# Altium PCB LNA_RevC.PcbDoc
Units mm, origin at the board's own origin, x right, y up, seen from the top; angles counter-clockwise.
Board outline 54 x 28 mm, 2 copper layers (Top Layer, Bottom Layer); 48 components, 25 nets, 118 pads, 134 vias.
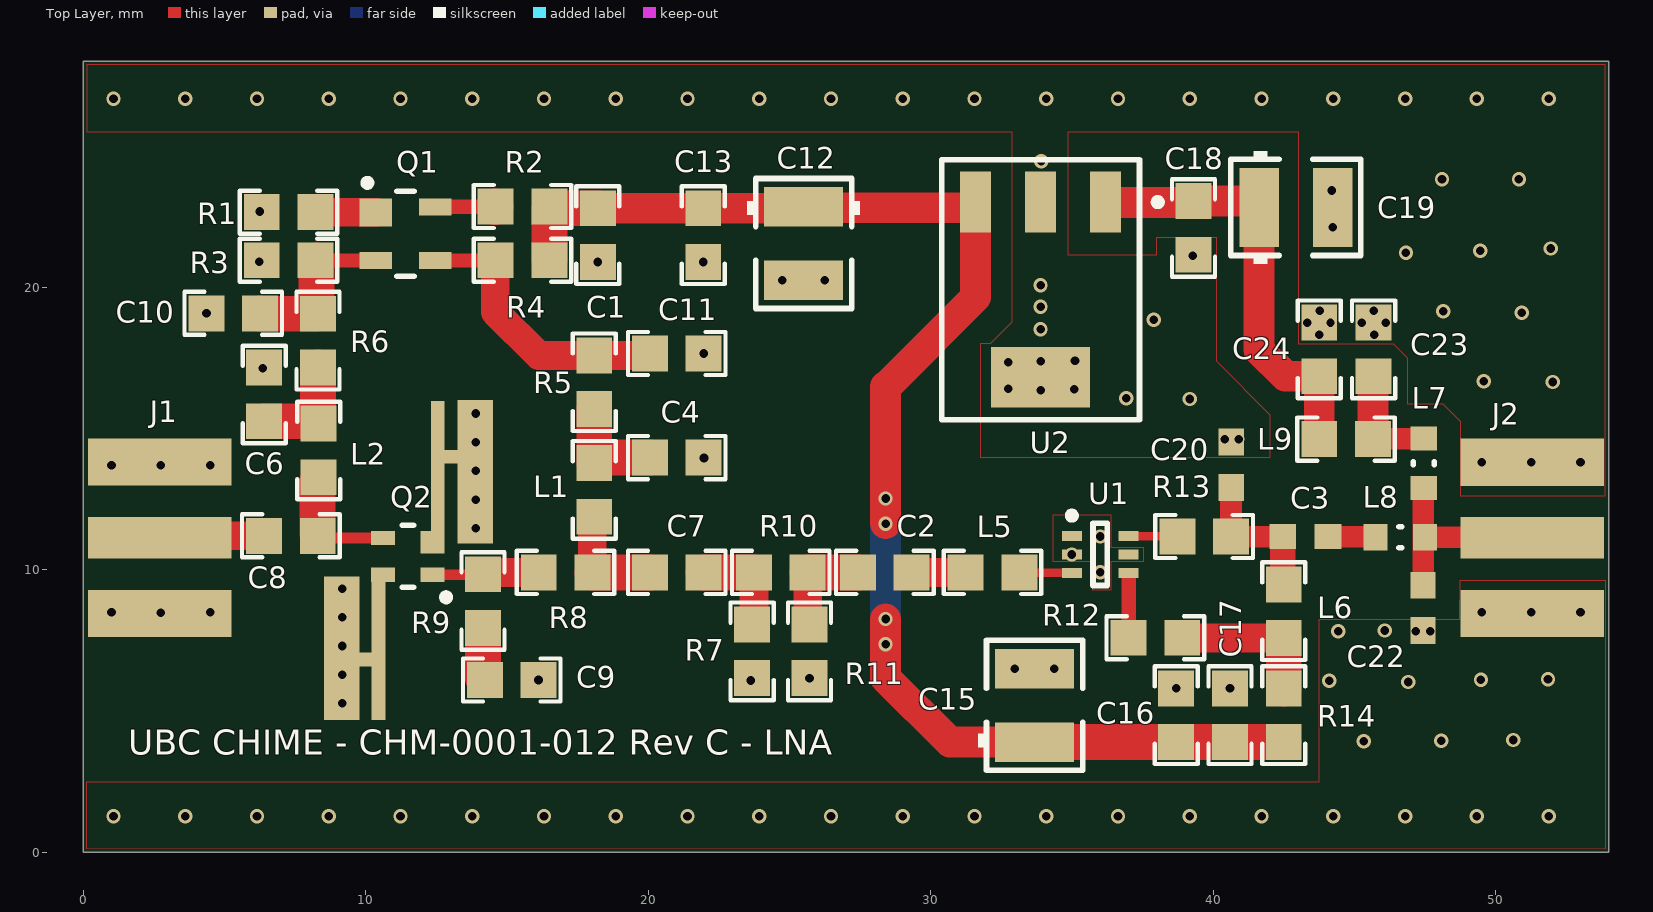
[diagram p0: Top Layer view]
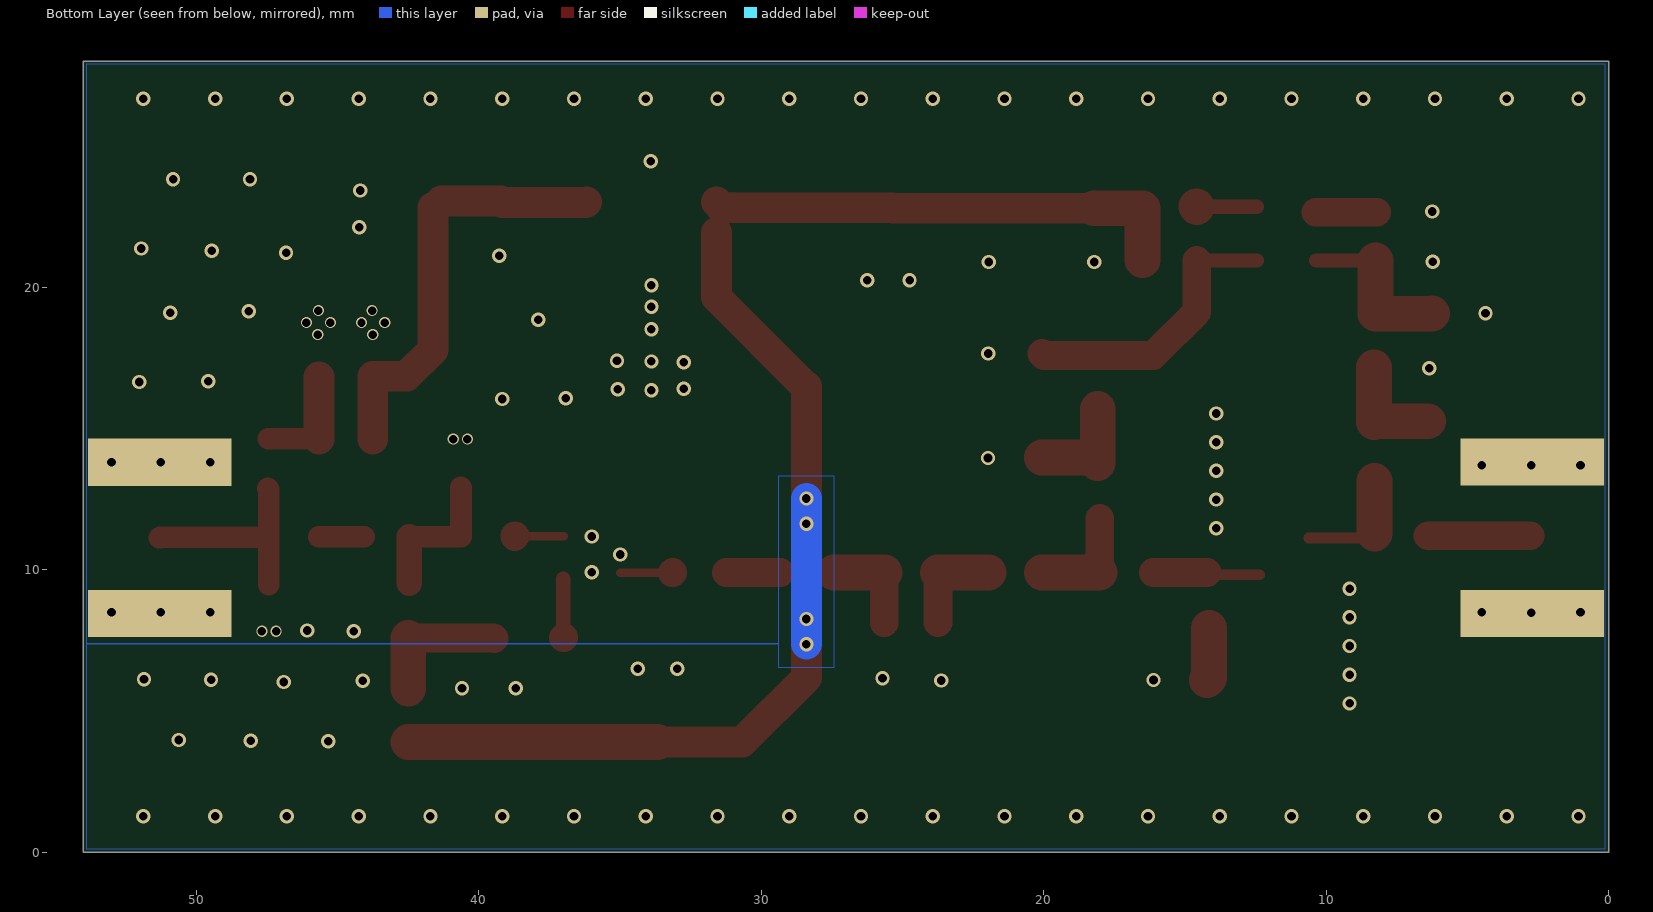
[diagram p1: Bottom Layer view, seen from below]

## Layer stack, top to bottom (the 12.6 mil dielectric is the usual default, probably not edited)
Top Solder: solder mask 0.0102, Solder Resist, Dk 3.5
Top Layer: signal copper 0.0356
Dielectric1: dielectric 0.32, FR-4, Dk 4.8
Bottom Layer: signal copper 0.0356
Bottom Solder: solder mask 0.0102, Solder Resist, Dk 3.5

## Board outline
0,0 0,28 54,28 54,0

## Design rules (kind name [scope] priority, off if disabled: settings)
AssemblyTestPointUsage [All] p0: scope1count=1 scope1_0_kind=Board scope1_0_value=Board scope2count=1 scope2_0_kind=Board scope2_0_value=Board commentlength=0
AssemblyTestpoint [All] p0: scope1count=1 scope1_0_kind=Board scope1_0_value=Board scope2count=1 scope2_0_kind=Board scope2_0_value=Board commentlength=0
Clearance [All] p0: scope1count=1 scope1_0_kind=Board scope1_0_value=Board scope2count=1 scope2_0_kind=Board scope2_0_value=Board commentlength=0 gap=0.1
Clearance Clearance_1 [All] p0: scope1count=1 scope1_0_kind=Board scope1_0_value=Board scope2count=1 scope2_0_kind=Board scope2_0_value=Board commentlength=0 gap=0.1
Clearance [All] p1: gap=0.1
Clearance Clearance_1 [All] p2: gap=0.1
ComponentClearance [All] p0: scope1count=1 scope1_0_kind=Board scope1_0_value=Board scope2count=1 scope2_0_kind=Board scope2_0_value=Board commentlength=0 gap=0 collisioncheckmode=3
ComponentClearance [All] p1: gap=0 collisioncheckmode=3 verticalgap=0 showdistances=FALSE
DiffPairsRouting [All] p0: scope1count=1 scope1_0_kind=Board scope1_0_value=Board scope2count=1 scope2_0_kind=Board scope2_0_value=Board commentlength=0
FabricationTestPointUsage [All] p0: scope1count=1 scope1_0_kind=Board scope1_0_value=Board scope2count=1 scope2_0_kind=Board scope2_0_value=Board commentlength=0 valid=0 allowmultiple=FALSE
FabricationTestpoint [All] p0: scope1count=1 scope1_0_kind=Board scope1_0_value=Board scope2count=1 scope2_0_kind=Board scope2_0_value=Board commentlength=0 side=3 testpointundercomponent=TRUE minsize=1.016 maxsize=2.54 preferedsize=1.524 minholesize=0 maxholesize=1.016 preferedholesize=0.813 testpointgrid=0.025
FanoutControl Fanout_BGA [All] p0 off: scope1count=1 scope1_0_kind=Board scope1_0_value=Board scope2count=1 scope2_0_kind=Board scope2_0_value=Board commentlength=69 // Protel DXP Scope 1 Expression Was: IsBGA   Fanout_BGA (Default Rule)
FanoutControl Fanout_LCC [All] p0 off: scope1count=1 scope1_0_kind=Board scope1_0_value=Board scope2count=1 scope2_0_kind=Board scope2_0_value=Board commentlength=69 // Protel DXP Scope 1 Expression Was: IsLCC   Fanout_LCC (Default Rule)
FanoutControl Fanout_SOIC [All] p0 off: scope1count=1 scope1_0_kind=Board scope1_0_value=Board scope2count=1 scope2_0_kind=Board scope2_0_value=Board commentlength=71 // Protel DXP Scope 1 Expression Was: IsSOIC   Fanout_SOIC (Default Rule)
FanoutControl Fanout_Small [All] p0 off: scope1count=1 scope1_0_kind=Board scope1_0_value=Board scope2count=1 scope2_0_kind=Board scope2_0_value=Board commentlength=84 // Protel DXP Scope 1 Expression Was: (CompPinCount < 5)   Fanout_Small (Default Rule)
FanoutControl Fanout_Default [All] p0: scope1count=1 scope1_0_kind=Board scope1_0_value=Board scope2count=1 scope2_0_kind=Board scope2_0_value=Board commentlength=30 // Fanout_Default (Default Rule)
Height [All] p0: scope1count=1 scope1_0_kind=Board scope1_0_value=Board scope2count=1 scope2_0_kind=Board scope2_0_value=Board commentlength=0
HoleSize [All] p0: scope1count=1 scope1_0_kind=Board scope1_0_value=Board scope2count=1 scope2_0_kind=Board scope2_0_value=Board commentlength=0 absolutevalues=TRUE maxlimit=5.54 minlimit=0.025 maxpercent=80.000 minpercent=20.000
HoleSize [All] p1: absolutevalues=TRUE maxlimit=5.54 minlimit=0.025 maxpercent=80.000 minpercent=20.000
HoleToHoleClearance [All] p0: scope1count=1 scope1_0_kind=Board scope1_0_value=Board scope2count=1 scope2_0_kind=Board scope2_0_value=Board commentlength=0
HoleToHoleClearance [All] p1: gap=0.1 allowstackedmicrovias=TRUE
LayerPairs [All] p0: scope1count=1 scope1_0_kind=Board scope1_0_value=Board scope2count=1 scope2_0_kind=Board scope2_0_value=Board commentlength=0 enforce=TRUE
MinimumSolderMaskSliver [All] p0: scope1count=1 scope1_0_kind=Board scope1_0_value=Board scope2count=1 scope2_0_kind=Board scope2_0_value=Board commentlength=0
MinimumSolderMaskSliver [All] p1: minsoldermaskwidth=0.01
NetAntennae [All] p0: scope1count=1 scope1_0_kind=Board scope1_0_value=Board scope2count=1 scope2_0_kind=Board scope2_0_value=Board commentlength=0
PasteMaskExpansion [All] p0: scope1count=1 scope1_0_kind=Board scope1_0_value=Board scope2count=1 scope2_0_kind=Board scope2_0_value=Board commentlength=0 expansion=0
PlaneClearance [All] p0: scope1count=1 scope1_0_kind=Board scope1_0_value=Board scope2count=1 scope2_0_kind=Board scope2_0_value=Board commentlength=0 clearance=0.2
PlaneClearance [All] p1: clearance=0.2
PlaneConnect [All] p0: scope1count=1 scope1_0_kind=Board scope1_0_value=Board scope2count=1 scope2_0_kind=Board scope2_0_value=Board commentlength=0 planeconnectstyle=Direct reliefexpansion=0.508 reliefentries=4 reliefconductorwidth=0.254 reliefairgap=0.254
PlaneConnect [All] p1: planeconnectstyle=Direct reliefexpansion=0.508 reliefentries=4 reliefconductorwidth=0.254 reliefairgap=0.254
PolygonConnect [All] p0: scope1count=1 scope1_0_kind=Board scope1_0_value=Board scope2count=1 scope2_0_kind=Board scope2_0_value=Board commentlength=0 connectstyle=Direct reliefconductorwidth=0.254 reliefentries=4 polygonreliefangle="90 Angle"
PolygonConnect [All] p1: connectstyle=Direct reliefconductorwidth=0.254 reliefentries=4 polygonreliefangle="90 Angle" airgapwidth=0.254
RoutingCorners [All] p0: scope1count=1 scope1_0_kind=Board scope1_0_value=Board scope2count=1 scope2_0_kind=Board scope2_0_value=Board commentlength=0 cornerstyle=45-Degree minsetback=2.54 maxsetback=2.54
RoutingLayers [All] p0: scope1count=1 scope1_0_kind=Board scope1_0_value=Board scope2count=1 scope2_0_kind=Board scope2_0_value=Board commentlength=0 top layer=Automatic bottom layer=Automatic
RoutingPriority [All] p0: scope1count=1 scope1_0_kind=Board scope1_0_value=Board scope2count=1 scope2_0_kind=Board scope2_0_value=Board commentlength=0
RoutingTopology [All] p0: scope1count=1 scope1_0_kind=Board scope1_0_value=Board scope2count=1 scope2_0_kind=Board scope2_0_value=Board commentlength=0 topology=Shortest
RoutingVias [All] p0: scope1count=1 scope1_0_kind=Board scope1_0_value=Board scope2count=1 scope2_0_kind=Board scope2_0_value=Board commentlength=0 holewidth=0.711 width=1.27 viastyle="Through Hole" minholewidth=0.711 minwidth=0.27 maxholewidth=0.711 maxwidth=5.27
RoutingVias [All] p1: holewidth=0.711 width=1.27 viastyle="Through Hole" minholewidth=0.711 minwidth=0.27 maxholewidth=0.711 maxwidth=5.27
ShortCircuit [All] p0: scope1count=1 scope1_0_kind=Board scope1_0_value=Board scope2count=1 scope2_0_kind=Board scope2_0_value=Board commentlength=0 allowed=FALSE
SilkToBoardRegionClearance [All] p0: scope1count=1 scope1_0_kind=Board scope1_0_value=Board scope2count=1 scope2_0_kind=Board scope2_0_value=Board commentlength=0
SilkToSilkClearance [All] p0: scope1count=1 scope1_0_kind=Board scope1_0_value=Board scope2count=1 scope2_0_kind=Board scope2_0_value=Board commentlength=0
SilkToSilkClearance [All] p1: silktosilkclearance=0
SilkToSolderMaskClearance SilkscreenOverComponentPads [All] p0 off: scope1count=1 scope1_0_kind=Board scope1_0_value=Board scope2count=1 scope2_0_kind=Board scope2_0_value=Board commentlength=44 // Protel DXP Scope 1 Expression Was: IsPad
SilkToSolderMaskClearance SilkscreenOverComponentPads [IsPad] p1: minsilkscreentomaskgap=0.01 clearancetoexposedcopper=TRUE
SolderMaskExpansion [All] p0: scope1count=1 scope1_0_kind=Board scope1_0_value=Board scope2count=1 scope2_0_kind=Board scope2_0_value=Board commentlength=0 expansion=0.05
SolderMaskExpansion [All] p1: expansion=0.05
UnRoutedNet [All] p0: scope1count=1 scope1_0_kind=Board scope1_0_value=Board scope2count=1 scope2_0_kind=Board scope2_0_value=Board commentlength=0
UnpouredPolygon [All] p0: scope1count=1 scope1_0_kind=Board scope1_0_value=Board scope2count=1 scope2_0_kind=Board scope2_0_value=Board commentlength=0
Width [All] p0: scope1count=1 scope1_0_kind=Board scope1_0_value=Board scope2count=1 scope2_0_kind=Board scope2_0_value=Board commentlength=0 maxlimit=25 minlimit=0.1 preferedwidth=0.254
Width [All] p1: maxlimit=25 minlimit=0.1 preferedwidth=0.254
22 further rules are at their usual default settings.

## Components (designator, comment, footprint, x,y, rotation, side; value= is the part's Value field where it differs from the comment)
C1 "C0805_1n" "0805 LRC" 18.215,21.844 r90 top
C2 "C0805_100p" "0805 LRC" 28.375,9.906 r0 top
C3 "C0603_2p7" C1608-0603 43.259,11.176 r180 top
C4 "C0805_15p" "0805 LRC" 21.009,13.97 r0 top
C6 "C0805_22p" "0805 LRC" 6.404,16.205 r270 top
C7 "C0805_1n" "0805 LRC" 21.009,9.906 r180 top
C8 "C0805_220p" "0805 LRC" 7.35,11.2 r0 top
C9 "C0805_2p2" "0805 LRC" 15.167,6.096 r180 top
C10 "C0805_1n" "0805 LRC" 5.312,19.075 r0 top
C11 "C0805_1n" "0805 LRC" 21.009,17.653 r180 top
C12 "Comment" CC3528 25.5,21.55 r270 top
C13 "C0805_u1" "0805 LRC" 21.949,21.844 r90 top
C15 "Comment" CC3528 33.675,5.2 r90 top
C16 "C0805_1n" "0805 LRC" 38.687,4.851 r90 top
C17 "C0805_u1" "0805 LRC" 40.592,4.851 r270 top
C18 "C0805_u1" "0805 LRC" 39.3,22.1 r90 top
C19 "Comment" CC3528 42.925,22.825 r0 top
C20 "C0603_3p9" C1608-0603 40.643,13.716 r270 top
C22 "C0603_2p7" C1608-0603 47.425,8.65 r90 top
C23 "C0805_1n" "0805 LRC" 45.675,17.8 r270 top
C24 "C0805_1n" "0805 LRC" 43.75,17.8 r270 top
J1 "SMA-Edgemount" SMA_EDGEMOUNT#1 2.859,11.128 r0 top
J2 "SMA-Edgemount" SMA_EDGEMOUNT#2 50.956,11.128 r0 top
L1 "Ind0805_22nH" "0805 LRC" 18.088,12.827 r90 top
L2 "Ind0805_82nH" "0805 LRC" 8.334,14.224 r90 top
L5 "Ind0805_6n8H" "0805 LRC" 32.185,9.906 r0 top
L6 "Ind0805_47nH" "0805 LRC" 42.497,8.534 r270 top
L7 "Ind0603_15nH" R0603 47.45,13.767 r90 top
L8 "Ind0603_15nH" R0603 46.625,11.15 r0 top
L9 "Ind0805_100nH" "0805 LRC" 44.7,14.625 r0 top
Q1 "BCV62" SOT143B_N 11.408,21.895 r0 top
Q2 "ATF-54143" SOT130P210X100-4AL 11.492,10.475 r180 top
R1 "R0805_3k32" "0805 LRC" 7.268,22.657 r0 top
R2 "R0805_511R" "0805 LRC" 15.548,22.86 r0 top
R3 "R0805_562R" "0805 LRC" 7.268,20.955 r0 top
R4 "R0805_10R" "0805 LRC" 15.548,20.955 r0 top
R5 "R0805_15R" "0805 LRC" 18.088,16.637 r90 top
R6 "R0805_100R" "0805 LRC" 8.309,18.11 r90 top
R7 "R0805" "0805 LRC" 23.676,7.112 r90 top
R8 "R0805_10R" "0805 LRC" 17.072,9.906 r0 top
R9 "R0805_12R7" "0805 LRC" 14.151,8.89 r90 top
R10 "R0805_0R" "0805 LRC" 24.692,9.906 r0 top
R11 "R0805" "0805 LRC" 25.708,7.112 r90 top
R12 "R0805_750R" "0805 LRC" 37.951,7.595 r0 top
R13 "R0805_0R" "0805 LRC" 39.678,11.176 r0 top
R14 "R0805_0R" "0805 LRC" 42.497,4.851 r270 top
U1 "MGA-62563" SOT-363/SC-70 35.995,10.541 r0 top
U2 "LT1129IST-5" SOT-223 33.887,19.914 r180 top

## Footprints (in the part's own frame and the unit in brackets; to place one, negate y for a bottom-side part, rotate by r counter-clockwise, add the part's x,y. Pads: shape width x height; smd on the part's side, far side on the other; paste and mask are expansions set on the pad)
"0805 LRC" [mm] "Generic 0805 reduced footprint"
  rect 1.27x1.27 smd: 1(-0.95,0) 2(0.95,0)
  silkscreen extent -1.73,-0.76 1.73,0.76
C1608-0603 [mm] "Chip Capacitor, 2-Leads, Body 1.60x0.80mm, IPC Medium Density"
  rect 0.95x0.9 smd: 1(-0.8,0) 2(0.8,0)
CC3528 [mm]
  rect 1.4x2.8 smd: 1(-1.3,0) 2(1.3,0)
  silkscreen extent -2.3,-2 2.3,2
R0603 [mm] "Chip Resistor, 2-Leads, Body 1.60x0.80mm, IPC Medium Density"
  rect 0.85x0.95 smd: 1(-0.875,0) 2(0.875,0)
  silkscreen extent -0.05,-0.38 0.05,0.38
SMA_EDGEMOUNT#1 [mm]
  rect 5.08x1.47 smd: 1(-0.159,0)
  rect 5.08x1.67 smd: 2(-0.159,-2.678) 2(-0.159,2.682)
  rect 5.08x1.67 smd far side: 2(-0.159,-2.678) 2(-0.159,2.682)
SMA_EDGEMOUNT#2 [mm]
  rect 5.08x1.47 smd: 1(0.344,0)
  rect 5.08x1.67 smd: 2(0.344,-2.681) 2(0.344,2.679)
  rect 5.08x1.67 smd far side: 2(0.344,-2.681) 2(0.344,2.679)
SOT130P210X100-4AL [mm] "SOT343, 4-Leads, Body 2x1.3 mm, Pitch 1.3mm, Lead Span 2.1mm, IPC High Density"
  rect 0.85x0.5 smd: 1(-0.875,0.65) 3(0.875,-0.65) 4(0.875,0.65)
  rect 0.85x0.8 smd: 2(-0.875,-0.5)
  silkscreen extent -1.48,-1.1 0.2,1.57
SOT143B_N [mm] "SOT143, 4-Leads, Body 2.9x1.3mm, Pitch 1.9mm, Lead Span 2.3mm, IPC Medium Density"
  rect 1.15x1 smd: 1(-1.05,0.75)
  rect 1.15x0.6 smd: 2(-1.05,-0.95) 3(1.05,-0.95) 4(1.05,0.95)
  silkscreen extent -1.47,-1.5 0.3,1.92
SOT-223 [mm]
  rect 1.1x2.15 smd: 1(-2.3,-3.1) 2(0,-3.1) 3(2.3,-3.1)
  rect 3.5x2.15 smd: 4(0,3.1)
  silkscreen extent -4.27,-4.6 3.5,4.6
SOT-363/SC-70 [mm] "SOT23, 6-Leads, Body 2.3x2.4mm (max), Pitch 0.65mm, IPC Medium Density"
  rect 0.7x0.35 smd: 1(-1,0.65) 2(-1,0) 3(-1,-0.65) 4(1,-0.65) 5(1,0) 6(1,0.65)
  silkscreen extent -1.12,-1.1 0.25,1.5

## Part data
C1 C7 C10 C11 C16 C23 C24: "1nF Ceramic NPO 0805 Capacitor"
C2: "100pF Ceramic NPO 0805 Capacitor"
C3 C22: "2.7pf  +- .1pf 50V NPO(COG)"
C4: "15pF Ceramic NPO 0805 Capacitor"
C6: "22pF Ceramic NPO 0805 Capacitor"
C8: library part C0805_100p, "220pF Ceramic NPO 0805 RF Capacitor"
C9: "2p2 Ceramic NPO 0805 Capacitor"
C12 C15 C19: library part "Cap Tant 10uF 25V B-Size Low ESR", "Cap Tant 10uF 25V Low ESR"
C13 C17 C18: "u1 Ceramic X7R 0805 Capacitor"
C20: "3.9pf  +-.1pf 0603 50V NPO"
J1 J2: library part "SMA LTI", "SMA long edge launch connectors female"
L1: "22nH 0805 Inductor"
L2: "82nH 0805 Inductor"
L5: "6n8H 0805 Inductor"
L6: "47nH 0805 Inductor"
L7 L8: "15nH 2% 0603"
L9: "100nH 0805 Inductor"
Q1: "PNP General-purpose Double Transistor"
Q2: "Avagotech GaAs FET enhancement pHEMT"
R1: "3k32 0805 0.1% 10ppm Resistor"
R2: "511R 0805 0.1% 10ppm Resistor"
R3: "562R 0805 0.1% 10ppm Resistor"
R4 R8: "10R 0805 0.1% 10ppm Resistor"
R5: "15R 0805 0.1% 10ppm Resistor"
R6: "100R 0805 0.1% 10ppm Resistor"
R7 R11: "??? 0805 1% Resistor"
R9: "12R7 0805 0.1% 10ppm Resistor"
R10 R13 R14: "0R 0805 1% Resistor"
R12: "750R 0805 0.1% 10ppm Resistor"
U1: "Low Noise RF Amplifier"
U2: "LDO +5V Regulator 700mA"

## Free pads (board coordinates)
  rect 1.27x5.08 smd: 0(9.15,7.225) 0(13.875,13.475)
  rect 1.016x0.483 smd: 2(9.925,6.825) 2(13.025,14)
  rect 0.483x5.334 smd: 2(10.45,7.35) 2(12.55,13.3)

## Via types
v1: diameter 0.508, hole 0.305, Top Layer to Bottom Layer, 109 vias
v2: diameter 0.508, hole 0.305, Top Layer to Bottom Layer, tented both sides, 13 vias
v3: diameter 0.4, hole 0.3, Top Layer to Bottom Layer, 12 vias

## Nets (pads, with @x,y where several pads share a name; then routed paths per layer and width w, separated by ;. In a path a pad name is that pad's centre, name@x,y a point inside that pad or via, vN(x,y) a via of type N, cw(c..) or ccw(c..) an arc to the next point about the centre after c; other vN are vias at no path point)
GND: C1.1 C4.2 C6.1 C9.1 C10.1 C11.1 C12.2 C13.1 C15.2 C16.2 C17.1 C18.1 C19.2 C20.1 C22.1 C23.1 C24.1 J1.2 J2.2 pad.0 pad.2 Q2.2 Q2.4 R1.1 R3.1 R7.1 R11.1 U1.1 U1.2 U1.5 U2.2 U2.4
  other v1: 1.07,1.27 3.61,1.27 6.15,1.27 8.69,1.27 11.23,1.27 13.77,1.27 16.31,1.27 18.85,1.27 21.39,1.27 23.93,1.27 26.47,1.27 29.01,1.27 31.55,1.27 34.09,1.27 36.63,1.27 39.17,1.27 41.71,1.27 44.25,1.27 46.79,1.27 49.33,1.27 51.87,1.27 45.325,3.925 48.075,3.95 50.625,3.975 9.175,5.268 38.687,5.801 40.592,5.801 46.9,6.025 23.625,6.081 44.1,6.075 16.117,6.096 49.475,6.1 51.85,6.125 25.708,6.162 9.175,6.284 32.975,6.5 34.375,6.5 9.175,7.3 44.425,7.825 46.075,7.85 9.175,8.316 2.75,8.475 1,8.5 4.5,8.5 49.5,8.5 51.25,8.5 53,8.5 9.175,9.332 13.9,11.468 13.9,12.484 13.9,13.5 1,13.7 2.75,13.7 4.5,13.7 49.5,13.8 51.25,13.8 53,13.8 21.974,13.955 13.9,14.516 13.9,15.532 39.17,16.045 36.92,16.07 52.02,16.645 49.57,16.67 6.353,17.13 21.959,17.653 37.895,18.845 4.362,19.075 50.92,19.095 48.145,19.145 24.75,20.25 26.25,20.25 6.226,20.904 18.215,20.894 21.949,20.894 39.27,21.12 46.82,21.22 49.445,21.295 51.945,21.37 44.225,22.125 6.252,22.682 44.2,23.425 48.095,23.82 50.82,23.82 1.07,26.67 3.61,26.67 6.15,26.67 8.69,26.67 11.23,26.67 13.77,26.67 16.31,26.67 18.85,26.67 21.39,26.67 23.93,26.67 26.47,26.67 29.01,26.67 31.55,26.67 34.09,26.67 36.63,26.67 39.17,26.67 41.71,26.67 44.25,26.67 46.79,26.67 49.33,26.67 51.87,26.67
  other v2: 35.995,9.906 34.995,10.541 35.995,11.176 33.887,16.358 35.081,16.383 32.744,16.408 32.744,17.348 33.887,17.374 35.106,17.399 33.887,18.517 33.887,19.304 33.887,20.066 33.912,24.46
  other v3: 47.175,7.825 47.675,7.825 40.4,14.625 40.9,14.625 43.75,18.325 45.7,18.325 43.325,18.75 44.15,18.75 45.25,18.75 46.1,18.75 43.775,19.175 45.675,19.175
NetC1_2: C1.2 C12.1 C13.2 C15.1 C16.1 C17.2 R2.2 R4.2 R14.2 U2.3 | length 50.9
  Top Layer w1.092: C1.2 C13.2 25.334,22.794 25.352,22.812 31.385,22.812 U2.3 ; v1@28.4,7.543 28.4,6.175 30.675,3.9 C15.1 ; v1@28.4,7.544 v1(28.4,8.255) ; v1(28.4,11.633) 28.4,12.344 v1(28.4,12.522) 28.4,16.485 ; 28.426,16.485 31.587,19.646 U2.3@31.587,21.947
  Top Layer w1.27: R4.2 16.498,22.794 C1.2 ; C15.1 33.676,3.901 C16.1 C17.2 R14.2
  Bottom Layer w1.092: v1(28.4,7.366) v1(28.4,8.255) v1(28.4,11.633) v1(28.4,12.522)
NetC2_1: C2.1 R10.2 R11.2 | length 3.6
  Top Layer w1.016: R11.2@25.642,8.128 R10.2
  Top Layer w1.27: R10.2 C2.1
NetC2_2: C2.2 L5.1 | length 1.9
  Top Layer w1.016: C2.2 L5.1
NetC3_1: C3.1 L8.1 | length 1.6
  Top Layer w0.762: C3.1 L8.1@45.661,11.176
NetC3_2: C3.2 C20.2 L6.1 R13.2 | length 5.3
  Top Layer w0.762: C20.2 40.628,12.901 R13.2 C3.2 ; L6.1@42.459,9.522 L6.1
  Top Layer w0.889: L6.1@42.459,9.522 C3.2
NetC4_1: C4.1 L1.2 R5.1 | length 4
  Top Layer w1.27: R5.1 L1.2 18.281,13.97 C4.1
NetC6_2: C6.2 L2.2 R6.1 | length 3.8
  Top Layer w0.254: C6.2@6.353,15.23 C6.2@6.384,15.199
  Top Layer w1.27: C6.2 L2.2@8.202,15.255 ; L2.2@8.309,15.225 R6.1
NetC7_1: C7.1 R7.2 R10.1 | length 3.6
  Top Layer w1.016: R7.2@23.742,8.128 R10.1
  Top Layer w1.27: C7.1 R10.1
NetC7_2: C7.2 L1.1 R8.2 | length 4
  Top Layer w0.254: L1.1@18.022,11.811 L1.1
  Top Layer w1.016: R8.2 L1.1@18.022,11.811
  Top Layer w1.27: R8.2 C7.2
NetC8_1: C8.1 J1.1 | length 3.6
  Top Layer w1.016: J1.1@2.778,11.2 C8.1
NetC8_2: C8.2 L2.1 Q2.3 | length 4.4
  Top Layer w0.254: C8.2@8.243,11.43 C8.2@8.548,11.125
  Top Layer w0.381: C8.2@8.548,11.125 Q2.3
  Top Layer w1.27: C8.2@8.294,11.278 8.294,11.742 8.294,12.672 L2.1@8.294,13.137
NetC9_2: C9.2 R9.1 | length 2.1
  Top Layer w0.254: C9.2@14.217,5.842 C9.2@14.405,6.03
  Top Layer w1.27: R9.1 14.151,6.162 C9.2
NetC10_2: C10.2 Q1.2 R3.2 R6.2 | length 6
  Top Layer w0.508: R3.2@8.263,20.945 Q1.2
  Top Layer w1.27: C10.2 6.277,19.06 8.263,19.06 R3.2@8.263,20.945
NetC11_2: C11.2 Q1.3 R4.1 R5.2 | length 10.1
  Top Layer w0.508: Q1.3 R4.1@14.588,20.945
  Top Layer w1.016: R4.1@14.588,20.945 14.588,19.121 16.122,17.587 R5.2 19.993,17.587 C11.2
NetC18_2: C18.2 C19.1 C24.2 L9.1 U2.1 | length 15
  Top Layer w1.092: U2.1 36.203,22.997 39.17,22.997 39.223,23.05 C19.1@41.325,23.05 ; C19.1 41.625,17.775 42.55,16.85 C24.2 L9.1
NetC22_2: C22.2 J2.1 L7.1 L8.2 | length 7.3
  Top Layer w0.762: C22.2@47.425,9.461 47.436,9.473 47.436,12.852 L7.1@47.476,12.892 ; L8.2 51.278,11.15 J2.1
NetC23_2: C23.2 L7.2 L9.2 | length 4
  Top Layer w0.762: L9.2 45.667,14.642 L7.2 ; C23.2@45.65,16.825 C23.2
  Top Layer w1.092: L9.2 C23.2@45.65,16.825
NetL5_2: L5.2 U1.3 | length 1.9
  Top Layer w0.305: L5.2@33.15,9.891 U1.3
  Top Layer w1.016: L5.2 L5.2@33.15,9.891
NetL6_2: L6.2 R12.2 R14.1 | length 4.8
  Top Layer w1.016: R12.2@39.46,7.569 39.475,7.584 L6.2
  Top Layer w1.27: R14.1 L6.2
NetQ1_1: Q1.1 R1.2 | length 2.2
  Top Layer w1.016: R1.2 Q1.1@10.371,22.657
NetQ1_4: Q1.4 R2.1 | length 2.1
  Top Layer w0.508: Q1.4 R2.1@14.583,22.845
  Top Layer w1.27: R2.1@14.583,22.845 R2.1
NetQ2_2: Q2.1 R8.1 R9.2 | length 3.5
  Top Layer w0.254: R9.2@13.882,9.825 R9.2@13.897,9.84 ; R9.2 R9.2@14.217,9.906
  Top Layer w0.381: Q2.1 R9.2@13.882,9.825
  Top Layer w1.016: R9.2@14.217,9.906 R8.1
NetR12_1: R12.1 U1.4 | length 2.1
  Top Layer w0.508: R12.1@37.011,7.626 37.011,9.677
  Top Layer w1.016: R12.1@36.995,7.6 R12.1
NetR13_1: R13.1 U1.6 | length 1.7
  Top Layer w0.305: U1.6 R13.1@38.713,11.191
  Top Layer w1.016: R13.1@38.713,11.191 R13.1

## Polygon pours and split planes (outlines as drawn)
GND on Top Layer "Top Layer-No Net 1" (solid, pour order 11): 53.875,9.625 53.875,0.125 53.85,0.15 0.125,0.125 0.125,2.5 43.75,2.5 43.75,8.25 46.4,8.25 48.725,8.25 48.75,9.625
GND on Top Layer "Top Layer-No Net" (solid, pour order 6): 34.344,11.938 36.376,11.938 36.376,10.795 37.519,10.795 37.519,10.287 36.376,10.287 36.376,9.271 35.741,9.271 35.741,10.287 34.344,10.287
GND on Top Layer "Top Solder-No Net" (solid, pour order 8): 0.125,27.875 0.125,25.5 32.875,25.5 32.865,18.765 32.1,18 31.75,18 31.75,13.975 42.025,13.975 42.025,15.475 40.125,17.375 40.125,21.75 37.975,21.75 37.975,21.125 34.875,21.125 34.875,25.5 43,25.5 43,18 46.375,18 46.875,17.5 46.875,15.875 48.125,15.875 48.75,15.25 48.75,12.625 53.875,12.625 53.875,27.875
GND on Top Solder "Bottom Layer-No Net" (solid, pour order 9): 0.125,2.5 0.125,0.125 53.875,0.125 53.875,2.5
GND on Top Solder "Bottom Layer-No Net" (solid, pour order 10): 0.125,27.875 0.125,25.5 53.875,25.5 53.875,27.875
GND on Bottom Layer "Top Layer-No Net" (solid, pour order 7): 0.125,27.9 53.9,27.9 53.9,7.375 29.375,7.375 29.375,13.325 27.425,13.325 27.425,6.525 29.375,6.525 29.375,7.375 53.9,7.4 53.9,0.125 0.125,0.125

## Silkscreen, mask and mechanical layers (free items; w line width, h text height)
Top Overlay:
  text "UBC CHIME - CHM-0001-012 Rev C - LNA" at 1.595,3.155 h1.52
Mechanical 1:
  the board outline again, w0.127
